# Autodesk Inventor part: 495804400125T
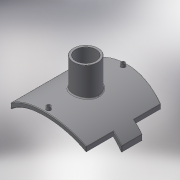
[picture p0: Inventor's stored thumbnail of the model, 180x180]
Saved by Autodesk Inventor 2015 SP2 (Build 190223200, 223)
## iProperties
Created: 2017-10
Part Number: 495804400125T
Material: Generic
Description: PLASSON BRANCH SADDLE 250-400X125
Document SubType Name: Modeling
Designer: KIM
Density: 1 g/cm^3
Appearance: Default
Author: KIM
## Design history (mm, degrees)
derived "495804 (SECOND).ipt"
feature "Solid1::495804 (SECOND).ipt"
tag "TaggingFeature1"
body "Solid1"
other parameters: "d1" = 15, "d2" = 274.5, "d4" = 0, "d5" = 305, "d6" = 75, "d7" = 0, "d8" = 135, "d10" = 0, "d11" = 2, "d12" = 225.6, "d13" = 14, "d14" = 135, "d16" = 5 deg, "d18" = 4, "d19" = 14, "d20" = 0, "d21" = 3, "d22" = 0, "d23" = 334, "d24" = 125, "d25" = 16, "d28" = 0, "d29" = 9.6, "d31" = 0, "d32" = 35.7, "d33" = 0, "d34" = 4, "d35" = 0.8, "d_1" = 125, "B_" = 305, "H_" = 119, "x_" = 15, "D_" = 16
